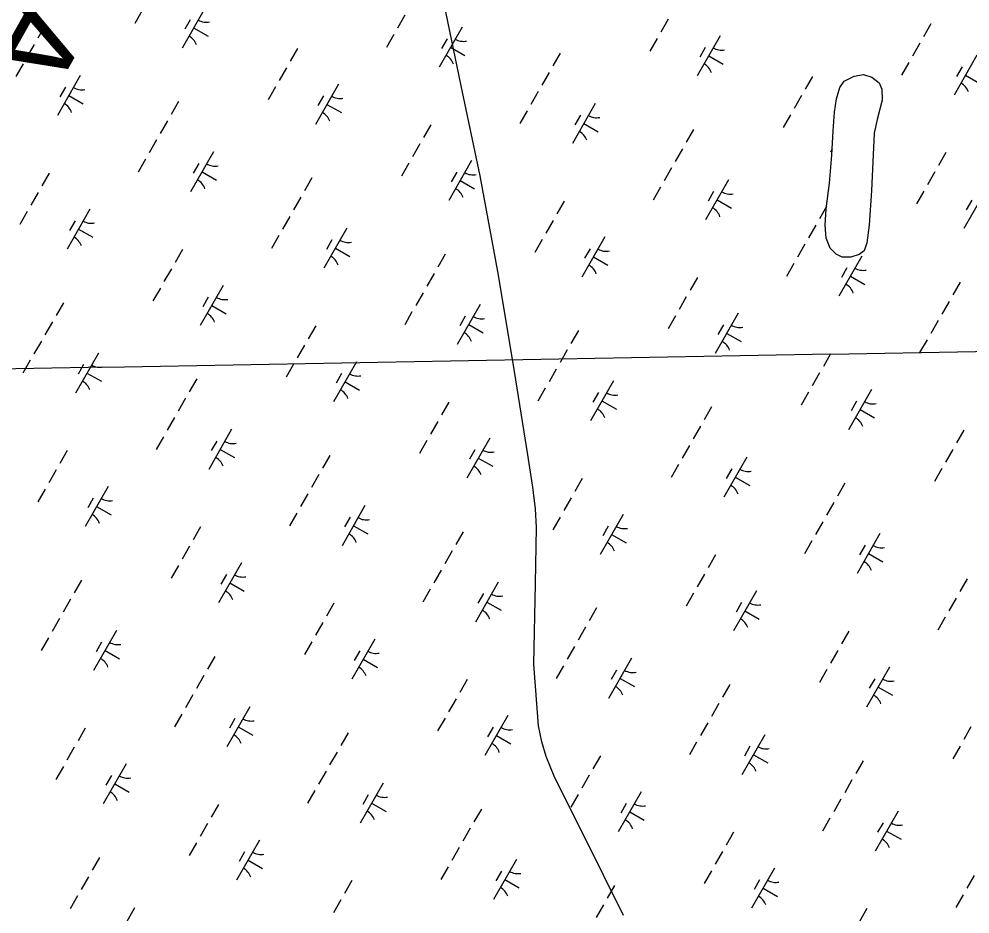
# Model space of a CAD drawing. Extents: x 3930721 to 3950824, y 220441 to 242861.
# Drawn here: x 3936799 to 3937829, y 229556 to 230526 of the extents above; entities that cross this region are included whole.
import ezdxf

# ---------------------------------------------------------------- set-up
doc = ezdxf.new("R2010")
doc.units = 0
for name, color, linetype in [('V-GRID-MAJR', 7, 'Continuous'), ('V-RIVR-IDEN', 7, 'Continuous'), ('V-TOPO-SHOR', 7, 'Continuous'), ('V-WETL-SWMP', 7, 'Continuous')]:
    doc.layers.add(name, color=color, linetype=linetype)

msp = doc.modelspace()

# ---------------------------------------------------------------- linework, layer by layer
at = {"layer": 'V-GRID-MAJR'}
msp.add_spline([(3935736.6, 230127.9), (3940756.9, 230218.1), (3946078.3, 230314.5), (3946614.6, 230324.3)], degree=3, dxfattribs=at)
at = {"layer": 'V-TOPO-SHOR'}
for points in [[(3937453.8, 229554.8), (3937410.6, 229641.9), (3937379.5, 229703.6), (3937370.1, 229726.7), (3937365.4, 229742.7), (3937361.6, 229759.9), (3937356.6, 229827), (3937358.3, 229914.1), (3937359.7, 229974.7), (3937358.6, 229995.1), (3937355.5, 230018.4), (3937350.2, 230053.7), (3937334.1, 230152.7), (3937317.8, 230252.1), (3937298.6, 230355.8), (3937278, 230453.1), (3937251.3, 230582.5)], [(3937725.3, 230401.9), (3937722.3, 230339.7), (3937719.8, 230302.3), (3937717.4, 230283.3), (3937714.3, 230274.6), (3937709.1, 230270.5), (3937700, 230267.5), (3937690.5, 230267.5), (3937684, 230270.9), (3937677.7, 230277.2), (3937673.1, 230288.1), (3937672, 230302.1), (3937673.2, 230319.9), (3937677, 230347.6), (3937679.4, 230378.1), (3937681, 230404.6), (3937682.4, 230424.7), (3937684.6, 230439.2), (3937688, 230451.2), (3937692.7, 230458.2), (3937703.6, 230463.5), (3937713.7, 230465.4), (3937722.8, 230462.7), (3937730.5, 230456.5), (3937733.5, 230449.6), (3937733.9, 230437.7), (3937728.5, 230416.8), (3937725.3, 230401.9)]]:
    msp.add_lwpolyline(points, dxfattribs=at)
at = {"layer": 'V-WETL-SWMP'}
for p, q in [((3936932.5, 230534.7), (3936924.6, 230520.8)), ((3937000.7, 230537.5), (3936975.8, 230494.1)), ((3936984.5, 230524.8), (3936978.6, 230514.4)), ((3937217, 230529.6), (3937209.1, 230515.7)), ((3937502.2, 230525.3), (3937494.3, 230511.4)), ((3936827.5, 230518.8), (3936819.5, 230504.9)), ((3936988.2, 230515.8), (3937003.9, 230506.8)), ((3937278.9, 230516.7), (3937254, 230473.3)), ((3937786.7, 230520.2), (3937778.8, 230506.3)), ((3937205.1, 230508.7), (3937197.2, 230494.8)), ((3937262.7, 230504.1), (3937256.8, 230493.6)), ((3937490.3, 230504.4), (3937482.3, 230490.6)), ((3937558.4, 230507.3), (3937533.6, 230463.9)), ((3936815.6, 230497.9), (3936807.6, 230484.1)), ((3937100.7, 230493.7), (3937092.8, 230479.8)), ((3937266.4, 230495), (3937282.1, 230486.1)), ((3937542.3, 230494.6), (3937536.3, 230484.2)), ((3937774.8, 230499.3), (3937766.8, 230485.4)), ((3937385.2, 230488.5), (3937377.3, 230474.7)), ((3937546, 230485.6), (3937561.6, 230476.6)), ((3937836.6, 230486.5), (3937811.8, 230443.1)), ((3936803.6, 230477.1), (3936795.7, 230463.2)), ((3937088.8, 230472.8), (3937080.9, 230458.9)), ((3937762.9, 230478.5), (3937754.9, 230464.6)), ((3937820.5, 230473.8), (3937814.5, 230463.4)), ((3936865.5, 230464.3), (3936840.6, 230420.9)), ((3937373.3, 230467.7), (3937365.4, 230453.8)), ((3937658.5, 230463.4), (3937650.5, 230449.5)), ((3937692.7, 230458.2), (3937703.6, 230463.5)), ((3937703.6, 230463.5), (3937713.7, 230465.4)), ((3937713.7, 230465.4), (3937722.8, 230462.7)), ((3937722.8, 230462.7), (3937730.5, 230456.5)), ((3937824.2, 230464.8), (3937839.8, 230455.8)), ((3936849.3, 230451.6), (3936843.4, 230441.2)), ((3937076.9, 230452), (3937068.9, 230438.1)), ((3937145, 230454.8), (3937120.2, 230411.4)), ((3937684.6, 230439.2), (3937688, 230451.2)), ((3937688, 230451.2), (3937692.7, 230458.2)), ((3937730.5, 230456.5), (3937733.5, 230449.6)), ((3937733.5, 230449.6), (3937733.9, 230437.7)), ((3936853, 230442.6), (3936868.7, 230433.6)), ((3937128.9, 230442.2), (3937122.9, 230431.8)), ((3937361.4, 230446.9), (3937353.4, 230433)), ((3937646.6, 230442.6), (3937638.6, 230428.7)), ((3937682.4, 230424.7), (3937684.6, 230439.2)), ((3936971.8, 230436.1), (3936963.9, 230422.2)), ((3937132.6, 230433.1), (3937148.2, 230424.2)), ((3937423.2, 230434), (3937398.4, 230390.7)), ((3937733.9, 230437.7), (3937728.5, 230416.8)), ((3937349.5, 230426.1), (3937341.5, 230412.2)), ((3937407.1, 230421.4), (3937401.1, 230411)), ((3937634.6, 230421.8), (3937626.7, 230407.9)), ((3937681, 230404.6), (3937682.4, 230424.7)), ((3936959.9, 230415.3), (3936952, 230401.4)), ((3937245.1, 230411), (3937237.1, 230397.1)), ((3937410.8, 230412.3), (3937426.4, 230403.4)), ((3937728.5, 230416.8), (3937725.3, 230401.9)), ((3937529.6, 230405.9), (3937521.6, 230392)), ((3937679.4, 230378.1), (3937681, 230404.6)), ((3937680.8, 230401.9), (3937680.6, 230401.5)), ((3937725.3, 230401.9), (3937722.3, 230339.7)), ((3936948, 230394.5), (3936940, 230380.6)), ((3937233.2, 230390.2), (3937225.2, 230376.3)), ((3937009.8, 230381.6), (3936985, 230338.2)), ((3937517.7, 230385.1), (3937509.7, 230371.2)), ((3937677, 230347.6), (3937679.4, 230378.1)), ((3937679.8, 230384.5), (3937677.9, 230381.2)), ((3937802.8, 230380.8), (3937794.9, 230366.9)), ((3936936.1, 230373.6), (3936928.1, 230359.7)), ((3936993.7, 230369), (3936987.7, 230358.5)), ((3937221.2, 230369.3), (3937213.3, 230355.5)), ((3937289.3, 230372.2), (3937264.5, 230328.8)), ((3936831.7, 230358.6), (3936823.7, 230344.7)), ((3936997.4, 230359.9), (3937013, 230351)), ((3937273.2, 230359.5), (3937267.2, 230349.1)), ((3937505.7, 230364.2), (3937497.8, 230350.3)), ((3937790.9, 230359.9), (3937782.9, 230346.1)), ((3937116.2, 230353.4), (3937108.2, 230339.6)), ((3937276.9, 230350.5), (3937292.5, 230341.5)), ((3937567.6, 230351.4), (3937542.7, 230308)), ((3937673.2, 230319.9), (3937677, 230347.6)), ((3936819.8, 230337.7), (3936811.8, 230323.8)), ((3937493.8, 230343.4), (3937485.9, 230329.5)), ((3937551.4, 230338.7), (3937545.5, 230328.3)), ((3937722.3, 230339.7), (3937719.8, 230302.3)), ((3937779, 230339.1), (3937771, 230325.2)), ((3937847.1, 230341.9), (3937822.2, 230298.5)), ((3937104.3, 230332.6), (3937096.3, 230318.7)), ((3937389.4, 230328.3), (3937381.5, 230314.4)), ((3937555.1, 230329.7), (3937570.8, 230320.7)), ((3937831, 230329.3), (3937825, 230318.9)), ((3936807.8, 230316.9), (3936799.9, 230303)), ((3936875.9, 230319.7), (3936851.1, 230276.3)), ((3937673.5, 230322.5), (3937666, 230309.3)), ((3937672, 230302.1), (3937673.2, 230319.9)), ((3936859.8, 230307.1), (3936853.8, 230296.6)), ((3937092.3, 230311.8), (3937084.4, 230297.9)), ((3937377.5, 230307.5), (3937369.5, 230293.6)), ((3936863.5, 230298), (3936879.1, 230289.1)), ((3937154.2, 230298.9), (3937129.3, 230255.6)), ((3937662, 230302.4), (3937654, 230288.5)), ((3937673.1, 230288.1), (3937672, 230302.1)), ((3937719.8, 230302.3), (3937717.4, 230283.3)), ((3937080.4, 230291), (3937072.4, 230277.1)), ((3937138, 230286.3), (3937132.1, 230275.9)), ((3937365.6, 230286.7), (3937357.6, 230272.8)), ((3937433.7, 230289.5), (3937408.8, 230246.1)), ((3937677.7, 230277.2), (3937673.1, 230288.1)), ((3936976, 230275.9), (3936968.1, 230262)), ((3937141.7, 230277.2), (3937157.3, 230268.3)), ((3937417.6, 230276.8), (3937411.6, 230266.4)), ((3937650.1, 230281.6), (3937642.1, 230267.7)), ((3937684, 230270.9), (3937677.7, 230277.2)), ((3937714.3, 230274.6), (3937709.1, 230270.5)), ((3937717.4, 230283.3), (3937714.3, 230274.6)), ((3937260.5, 230270.8), (3937252.6, 230256.9)), ((3937421.3, 230267.8), (3937436.9, 230258.8)), ((3937690.5, 230267.5), (3937684, 230270.9)), ((3937711.9, 230268.7), (3937687, 230225.3)), ((3937700, 230267.5), (3937690.5, 230267.5)), ((3937709.1, 230270.5), (3937700, 230267.5)), ((3936964.1, 230255.1), (3936956.1, 230241.2)), ((3937638.1, 230260.7), (3937630.2, 230246.8)), ((3937695.8, 230256.1), (3937689.8, 230245.6)), ((3937248.6, 230249.9), (3937240.6, 230236.1)), ((3937533.8, 230245.7), (3937525.8, 230231.8)), ((3937699.5, 230247), (3937715.1, 230238.1)), ((3936952.2, 230234.2), (3936944.2, 230220.4)), ((3937020.3, 230237), (3936995.4, 230193.7)), ((3937818.3, 230240.5), (3937810.3, 230226.7)), ((3937004.1, 230224.4), (3936998.2, 230214)), ((3937236.7, 230229.1), (3937228.7, 230215.2)), ((3937521.8, 230224.8), (3937513.9, 230210.9)), ((3936847.1, 230218.3), (3936839.2, 230204.5)), ((3937007.9, 230215.4), (3937023.5, 230206.4)), ((3937298.5, 230216.3), (3937273.6, 230172.9)), ((3937806.3, 230219.7), (3937798.4, 230205.8)), ((3937224.7, 230208.3), (3937216.8, 230194.4)), ((3937282.4, 230203.6), (3937276.4, 230193.2)), ((3937509.9, 230204), (3937502, 230190.1)), ((3937578, 230206.8), (3937553.2, 230163.4)), ((3936835.2, 230197.5), (3936827.2, 230183.6)), ((3937120.4, 230193.2), (3937112.4, 230179.3)), ((3937286.1, 230194.6), (3937301.7, 230185.6)), ((3937561.9, 230194.2), (3937555.9, 230183.8)), ((3937794.4, 230198.9), (3937786.5, 230185)), ((3937404.9, 230188.1), (3937396.9, 230174.2)), ((3937565.6, 230185.1), (3937581.2, 230176.2)), ((3936823.3, 230176.7), (3936815.3, 230162.8)), ((3937108.4, 230172.4), (3937100.5, 230158.5)), ((3937782.5, 230178.1), (3937774.5, 230164.2)), ((3936885.1, 230163.8), (3936860.2, 230120.4)), ((3937392.9, 230167.3), (3937385, 230153.4)), ((3937678.1, 230163), (3937670.2, 230149.1)), ((3936811.3, 230155.9), (3936803.4, 230142)), ((3936869, 230151.2), (3936863, 230140.8)), ((3937096.5, 230151.6), (3937088.6, 230137.7)), ((3937164.6, 230154.4), (3937139.8, 230111)), ((3936872.7, 230142.1), (3936888.3, 230133.2)), ((3937148.5, 230141.7), (3937142.5, 230131.3)), ((3937381, 230146.5), (3937373.1, 230132.6)), ((3937666.2, 230142.2), (3937658.2, 230128.3)), ((3936991.5, 230135.7), (3936983.5, 230121.8)), ((3937152.2, 230132.7), (3937167.8, 230123.7)), ((3937442.8, 230133.6), (3937418, 230090.2)), ((3937369.1, 230125.6), (3937361.1, 230111.7)), ((3937426.7, 230121), (3937420.7, 230110.5)), ((3937654.2, 230121.3), (3937646.3, 230107.5)), ((3937722.4, 230124.2), (3937697.5, 230080.8)), ((3936979.5, 230114.8), (3936971.6, 230101)), ((3937264.7, 230110.6), (3937256.8, 230096.7)), ((3937430.4, 230111.9), (3937446, 230103)), ((3937706.2, 230111.5), (3937700.3, 230101.1)), ((3937549.2, 230105.4), (3937541.3, 230091.6)), ((3937709.9, 230102.5), (3937725.6, 230093.5)), ((3936967.6, 230094), (3936959.7, 230080.1)), ((3937252.8, 230089.7), (3937244.8, 230075.8)), ((3937029.4, 230081.2), (3937004.6, 230037.8)), ((3937537.3, 230084.6), (3937529.3, 230070.7)), ((3937822.4, 230080.3), (3937814.5, 230066.4)), ((3936955.7, 230073.2), (3936947.7, 230059.3)), ((3937013.3, 230068.5), (3937007.3, 230058.1)), ((3937240.8, 230068.9), (3937232.9, 230055)), ((3937309, 230071.7), (3937284.1, 230028.3)), ((3936851.3, 230058.1), (3936843.3, 230044.2)), ((3937017, 230059.5), (3937032.6, 230050.5)), ((3937292.8, 230059.1), (3937286.9, 230048.7)), ((3937525.4, 230063.8), (3937517.4, 230049.9)), ((3937810.5, 230059.5), (3937802.6, 230045.6)), ((3937135.8, 230053), (3937127.9, 230039.1)), ((3937296.5, 230050), (3937312.2, 230041.1)), ((3937587.2, 230050.9), (3937562.3, 230007.6)), ((3937513.4, 230043), (3937505.5, 230029.1)), ((3937571, 230038.3), (3937565.1, 230027.9)), ((3937798.6, 230038.7), (3937790.6, 230024.8)), ((3936839.4, 230037.3), (3936831.4, 230023.4)), ((3937123.9, 230032.2), (3937115.9, 230018.3)), ((3937409, 230027.9), (3937401.1, 230014)), ((3937574.8, 230029.2), (3937590.4, 230020.3)), ((3936895.6, 230019.3), (3936870.7, 229975.9)), ((3937693.5, 230022.8), (3937685.6, 230008.9)), ((3936827.4, 230016.5), (3936819.5, 230002.6)), ((3936879.4, 230006.6), (3936873.5, 229996.2)), ((3937112, 230011.4), (3937104, 229997.5)), ((3937397.1, 230007.1), (3937389.2, 229993.2)), ((3936883.1, 229997.6), (3936898.8, 229988.6)), ((3937173.8, 229998.5), (3937148.9, 229955.1)), ((3937681.6, 230001.9), (3937673.7, 229988.1)), ((3937100, 229990.5), (3937092.1, 229976.6)), ((3937157.6, 229985.9), (3937151.7, 229975.4)), ((3937385.2, 229986.2), (3937377.2, 229972.4)), ((3937453.3, 229989.1), (3937428.5, 229945.7)), ((3937161.4, 229976.8), (3937177, 229967.9)), ((3937437.2, 229976.4), (3937431.2, 229966)), ((3937669.7, 229981.1), (3937661.7, 229967.2)), ((3936995.6, 229975.5), (3936987.7, 229961.6)), ((3937280.1, 229970.3), (3937272.2, 229956.5)), ((3937440.9, 229967.4), (3937456.5, 229958.4)), ((3937731.5, 229968.3), (3937706.7, 229924.9)), ((3937657.8, 229960.3), (3937649.8, 229946.4)), ((3937715.4, 229955.6), (3937709.4, 229945.2)), ((3936983.7, 229954.6), (3936975.8, 229940.7)), ((3937268.2, 229949.5), (3937260.3, 229935.6)), ((3937553.4, 229945.2), (3937545.4, 229931.3)), ((3937719.1, 229946.6), (3937734.7, 229937.6)), ((3937039.9, 229936.6), (3937015.1, 229893.2)), ((3936971.8, 229933.8), (3936963.8, 229919.9)), ((3937256.3, 229928.7), (3937248.3, 229914.8)), ((3937541.5, 229924.4), (3937533.5, 229910.5)), ((3936866.7, 229917.9), (3936858.8, 229904)), ((3937023.8, 229924), (3937017.8, 229913.5)), ((3937027.5, 229914.9), (3937043.1, 229906)), ((3937318.1, 229915.8), (3937293.3, 229872.5)), ((3937826, 229919.3), (3937818, 229905.4)), ((3937244.4, 229907.9), (3937236.4, 229894)), ((3937529.5, 229903.6), (3937521.6, 229889.7)), ((3937597.7, 229906.4), (3937572.8, 229863)), ((3936854.8, 229897.1), (3936846.9, 229883.2)), ((3937302, 229903.2), (3937296, 229892.8)), ((3937305.7, 229894.1), (3937321.3, 229885.2)), ((3937581.5, 229893.7), (3937575.6, 229883.3)), ((3937814, 229898.5), (3937806.1, 229884.6)), ((3937140, 229892.8), (3937132, 229878.9)), ((3937424.5, 229887.7), (3937416.5, 229873.8)), ((3937585.2, 229884.7), (3937600.8, 229875.7)), ((3936842.9, 229876.3), (3936834.9, 229862.4)), ((3937802.1, 229877.6), (3937794.2, 229863.7)), ((3936904.7, 229863.4), (3936879.9, 229820)), ((3937128.1, 229872), (3937120.1, 229858.1)), ((3937412.6, 229866.8), (3937404.6, 229853)), ((3937697.7, 229862.6), (3937689.8, 229848.7)), ((3936831, 229855.4), (3936823, 229841.5)), ((3937184.3, 229853.9), (3937159.4, 229810.6)), ((3936888.6, 229850.8), (3936882.6, 229840.3)), ((3936892.3, 229841.7), (3936907.9, 229832.8)), ((3937116.1, 229851.1), (3937108.2, 229837.3)), ((3937400.6, 229846), (3937392.7, 229832.1)), ((3937685.8, 229841.7), (3937677.8, 229827.8)), ((3937011.1, 229835.2), (3937003.1, 229821.4)), ((3937168.1, 229841.3), (3937162.1, 229830.9)), ((3937171.8, 229832.3), (3937187.4, 229823.3)), ((3937462.5, 229833.2), (3937437.6, 229789.8)), ((3937388.7, 229825.2), (3937380.8, 229811.3)), ((3937742, 229823.7), (3937717.1, 229780.3)), ((3936999.2, 229814.4), (3936991.2, 229800.5)), ((3937446.3, 229820.5), (3937440.4, 229810.1)), ((3937450, 229811.5), (3937465.7, 229802.5)), ((3937673.9, 229820.9), (3937665.9, 229807)), ((3937725.9, 229811.1), (3937719.9, 229800.7)), ((3937284.3, 229810.1), (3937276.4, 229796.2)), ((3937568.8, 229805), (3937560.9, 229791.1)), ((3937729.6, 229802), (3937745.2, 229793.1)), ((3936987.2, 229793.6), (3936979.3, 229779.7)), ((3937049.1, 229780.7), (3937024.2, 229737.3)), ((3937272.4, 229789.3), (3937264.4, 229775.4)), ((3937556.9, 229784.2), (3937549, 229770.3)), ((3936975.3, 229772.8), (3936967.4, 229758.9)), ((3937328.6, 229771.3), (3937303.7, 229727.9)), ((3937032.9, 229768.1), (3937027, 229757.7)), ((3937260.5, 229768.5), (3937252.5, 229754.6)), ((3937545, 229763.4), (3937537, 229749.5)), ((3936870.9, 229757.7), (3936863, 229743.8)), ((3937036.6, 229759), (3937052.3, 229750.1)), ((3937155.4, 229752.6), (3937147.5, 229738.7)), ((3937312.5, 229758.6), (3937306.5, 229748.2)), ((3937316.2, 229749.6), (3937331.8, 229740.6)), ((3937606.8, 229750.5), (3937582, 229707.1)), ((3937830.1, 229759.1), (3937822.2, 229745.2)), ((3937533, 229742.5), (3937525.1, 229728.6)), ((3936859, 229736.9), (3936851, 229723)), ((3937143.5, 229731.7), (3937135.5, 229717.9)), ((3937590.7, 229737.9), (3937584.7, 229727.4)), ((3937594.4, 229728.8), (3937610, 229719.9)), ((3937818.2, 229738.2), (3937810.3, 229724.4)), ((3936915.2, 229718.8), (3936890.3, 229675.5)), ((3937428.7, 229727.5), (3937420.7, 229713.6)), ((3937713.2, 229722.3), (3937705.2, 229708.5)), ((3936847.1, 229716), (3936839.1, 229702.1)), ((3937131.6, 229710.9), (3937123.6, 229697)), ((3936899.1, 229706.2), (3936893.1, 229695.8)), ((3937193.4, 229698.1), (3937168.6, 229654.7)), ((3937416.7, 229706.6), (3937408.8, 229692.7)), ((3937701.2, 229701.5), (3937693.3, 229687.6)), ((3936902.8, 229697.2), (3936918.4, 229688.2)), ((3937119.6, 229690.1), (3937111.7, 229676.2)), ((3937472.9, 229688.6), (3937448.1, 229645.2)), ((3937177.3, 229685.4), (3937171.3, 229675)), ((3937404.8, 229685.8), (3937396.9, 229671.9)), ((3937689.3, 229680.7), (3937681.4, 229666.8)), ((3937015.3, 229675), (3937007.3, 229661.1)), ((3937181, 229676.4), (3937196.6, 229667.4)), ((3937299.8, 229669.9), (3937291.8, 229656)), ((3937456.8, 229676), (3937450.8, 229665.5)), ((3937460.5, 229666.9), (3937476.1, 229658)), ((3937751.1, 229667.8), (3937726.3, 229624.5)), ((3937677.4, 229659.9), (3937669.4, 229646)), ((3937003.3, 229654.2), (3936995.4, 229640.3)), ((3937287.8, 229649.1), (3937279.9, 229635.2)), ((3937735, 229655.2), (3937729, 229644.8)), ((3937738.7, 229646.1), (3937754.3, 229637.2)), ((3937059.5, 229636.2), (3937034.7, 229592.8)), ((3937573, 229644.8), (3937565.1, 229630.9)), ((3936991.4, 229633.4), (3936983.5, 229619.5)), ((3937275.9, 229628.3), (3937268, 229614.4)), ((3936886.4, 229617.5), (3936878.4, 229603.6)), ((3937043.4, 229623.5), (3937037.4, 229613.1)), ((3937337.7, 229615.4), (3937312.9, 229572)), ((3937561.1, 229624), (3937553.1, 229610.1)), ((3937047.1, 229614.5), (3937062.7, 229605.5)), ((3937264, 229607.4), (3937256, 229593.5)), ((3937617.3, 229605.9), (3937592.4, 229562.6)), ((3936874.4, 229596.6), (3936866.5, 229582.8)), ((3937321.6, 229602.8), (3937315.6, 229592.3)), ((3937549.2, 229603.1), (3937541.2, 229589.3)), ((3937833.7, 229598), (3937825.7, 229584.1)), ((3937159.6, 229592.4), (3937151.7, 229578.5)), ((3937325.3, 229593.7), (3937340.9, 229584.8)), ((3937444.1, 229587.2), (3937436.2, 229573.4)), ((3937601.1, 229593.3), (3937595.2, 229582.9)), ((3937604.9, 229584.3), (3937620.5, 229575.3)), ((3936862.5, 229575.8), (3936854.6, 229561.9)), ((3937821.7, 229577.2), (3937813.8, 229563.3)), ((3937147.7, 229571.5), (3937139.7, 229557.6)), ((3937432.2, 229566.4), (3937424.2, 229552.5)), ((3936924.3, 229563), (3936899.5, 229519.6)), ((3937717.4, 229562.1), (3937709.4, 229548.2))]:
    msp.add_line(p, q, dxfattribs=at)
for centre, start, end in [((3937002.2, 230539.6), 239.4279, 280.9715), ((3936974.7, 230491.7), 19.4279, 60.9715), ((3937280.4, 230518.9), 239.4279, 280.9715), ((3937559.9, 230509.4), 239.4279, 280.9715), ((3937252.9, 230470.9), 19.4279, 60.9715), ((3937532.5, 230461.5), 19.4279, 60.9715), ((3936867, 230466.4), 239.4279, 280.9715), ((3937810.7, 230440.7), 19.4279, 60.9715), ((3937146.5, 230457), 239.4279, 280.9715), ((3936839.5, 230418.5), 19.4279, 60.9715), ((3937119.1, 230409), 19.4279, 60.9715), ((3937424.7, 230436.2), 239.4279, 280.9715), ((3937397.3, 230388.3), 19.4279, 60.9715), ((3937011.3, 230383.8), 239.4279, 280.9715), ((3937290.9, 230374.3), 239.4279, 280.9715), ((3936983.9, 230335.8), 19.4279, 60.9715), ((3937263.4, 230326.4), 19.4279, 60.9715), ((3937569.1, 230353.5), 239.4279, 280.9715), ((3937541.6, 230305.6), 19.4279, 60.9715), ((3936877.5, 230321.9), 239.4279, 280.9715), ((3936850, 230273.9), 19.4279, 60.9715), ((3937155.7, 230301.1), 239.4279, 280.9715), ((3937435.2, 230291.6), 239.4279, 280.9715), ((3937128.2, 230253.2), 19.4279, 60.9715), ((3937407.7, 230243.7), 19.4279, 60.9715), ((3937713.4, 230270.9), 239.4279, 280.9715), ((3937686, 230222.9), 19.4279, 60.9715), ((3937021.8, 230239.2), 239.4279, 280.9715), ((3936994.3, 230191.3), 19.4279, 60.9715), ((3937300, 230218.4), 239.4279, 280.9715), ((3937579.5, 230209), 239.4279, 280.9715), ((3937272.6, 230170.5), 19.4279, 60.9715), ((3937552.1, 230161), 19.4279, 60.9715), ((3936886.6, 230166), 239.4279, 280.9715), ((3937166.1, 230156.5), 239.4279, 280.9715), ((3936859.1, 230118.1), 19.4279, 60.9715), ((3937138.7, 230108.6), 19.4279, 60.9715), ((3937444.3, 230135.8), 239.4279, 280.9715), ((3937723.9, 230126.3), 239.4279, 280.9715), ((3937416.9, 230087.8), 19.4279, 60.9715), ((3937696.4, 230078.4), 19.4279, 60.9715), ((3937030.9, 230083.3), 239.4279, 280.9715), ((3937310.5, 230073.9), 239.4279, 280.9715), ((3937003.5, 230035.4), 19.4279, 60.9715), ((3937283, 230025.9), 19.4279, 60.9715), ((3937588.7, 230053.1), 239.4279, 280.9715), ((3937561.2, 230005.2), 19.4279, 60.9715), ((3936897.1, 230021.4), 239.4279, 280.9715), ((3936869.6, 229973.5), 19.4279, 60.9715), ((3937175.3, 230000.7), 239.4279, 280.9715), ((3937454.8, 229991.2), 239.4279, 280.9715), ((3937147.8, 229952.7), 19.4279, 60.9715), ((3937427.4, 229943.3), 19.4279, 60.9715), ((3937733, 229970.4), 239.4279, 280.9715), ((3937705.6, 229922.5), 19.4279, 60.9715), ((3937041.4, 229938.8), 239.4279, 280.9715), ((3937014, 229890.8), 19.4279, 60.9715), ((3937319.6, 229918), 239.4279, 280.9715), ((3937599.2, 229908.5), 239.4279, 280.9715), ((3937292.2, 229870.1), 19.4279, 60.9715), ((3937571.7, 229860.6), 19.4279, 60.9715), ((3936906.2, 229865.6), 239.4279, 280.9715), ((3936878.8, 229817.6), 19.4279, 60.9715), ((3937185.8, 229856.1), 239.4279, 280.9715), ((3937158.3, 229808.2), 19.4279, 60.9715), ((3937464, 229835.3), 239.4279, 280.9715), ((3937436.5, 229787.4), 19.4279, 60.9715), ((3937743.5, 229825.9), 239.4279, 280.9715), ((3937716, 229777.9), 19.4279, 60.9715), ((3937050.6, 229782.9), 239.4279, 280.9715), ((3937023.1, 229735), 19.4279, 60.9715), ((3937330.1, 229773.4), 239.4279, 280.9715), ((3937302.6, 229725.5), 19.4279, 60.9715), ((3937608.3, 229752.7), 239.4279, 280.9715), ((3937580.9, 229704.7), 19.4279, 60.9715), ((3936916.7, 229721), 239.4279, 280.9715), ((3936889.2, 229673.1), 19.4279, 60.9715), ((3937194.9, 229700.2), 239.4279, 280.9715), ((3937167.5, 229652.3), 19.4279, 60.9715), ((3937474.4, 229690.8), 239.4279, 280.9715), ((3937447, 229642.8), 19.4279, 60.9715), ((3937752.7, 229670), 239.4279, 280.9715), ((3937725.2, 229622.1), 19.4279, 60.9715), ((3937061, 229638.3), 239.4279, 280.9715), ((3937033.6, 229590.4), 19.4279, 60.9715), ((3937339.3, 229617.6), 239.4279, 280.9715), ((3937311.8, 229569.6), 19.4279, 60.9715), ((3937618.8, 229608.1), 239.4279, 280.9715), ((3937591.3, 229560.2), 19.4279, 60.9715)]:
    msp.add_arc(centre, 17.6, start, end, dxfattribs=at)

# ---------------------------------------------------------------- texts
at = {"layer": 'V-RIVR-IDEN'}
msp.add_text('B   A   Y', height=100, rotation=240.6031, dxfattribs=at).set_placement((3936889.1, 230740.5))

doc.saveas('drawing.dxf')
